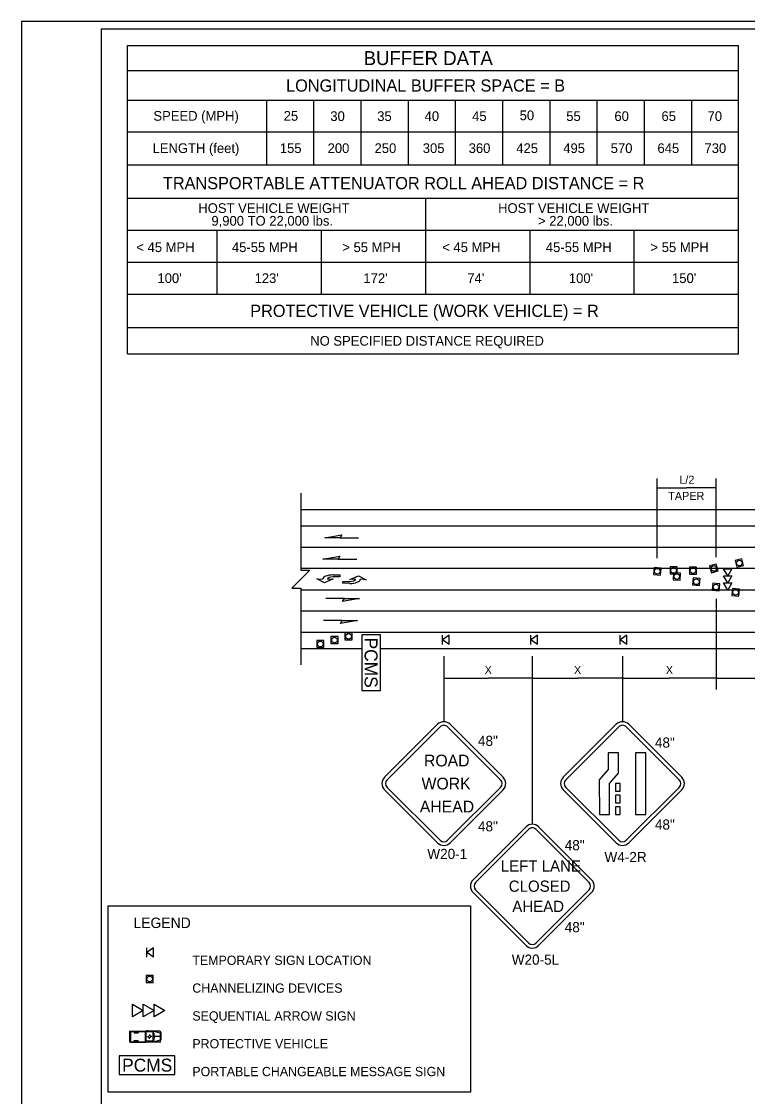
# Model space of a CAD drawing. Extents: x 99988 to 100172, y 99995 to 100047.
# Drawn here: x 99999.31 to 100005.58, y 100001.16 to 100010.44 of the extents above; entities that cross this region are included whole.
import ezdxf

# ---------------------------------------------------------------- set-up
doc = ezdxf.new("R2010")
doc.units = 0
for name, color, linetype in [('Default', 7, 'Continuous'), ('Level 15', 7, 'Continuous'), ('Level 20', 7, 'Continuous'), ('RD_MK_TrafficArrowType2LNew', 7, 'Continuous'), ('SH_DE_DetailBody1Text', 7, 'Continuous'), ('SH_DE_DetailHeading2Text', 7, 'Continuous'), ('SH_GI_PlotLimits', 7, 'Continuous'), ('SH_GI_SheetBorder', 7, 'Continuous'), ('SH_GI_TrafficMvmntArrowRt1Lane', 7, 'Continuous'), ('SH_TI_BufferDataNote', 7, 'Continuous'), ('SH_TI_SignSpacing35to70Note', 7, 'Continuous'), ('TR_SN_WarningSigns', 7, 'Continuous'), ('TR_WZ_PortableChangeMessageSign', 7, 'Continuous'), ('TR_WZ_SequentialArrowTypeC', 7, 'Continuous'), ('TR_WZ_TrafficSafetyCone', 7, 'Continuous'), ('TR_WZ_TruckBuffer', 7, 'Continuous'), ('TR_WZ_WorkZoneDetails', 7, 'Continuous')]:
    doc.layers.add(name, color=color, linetype=linetype)

msp = doc.modelspace()

# ---------------------------------------------------------------- linework, layer by layer
at = {"layer": 'Default'}
for p, q in [((100013.6062, 100005.718), (100001.7239, 100005.7184)), ((100003.0033, 100005.1415), (100002.9456, 100005.1012)), ((100002.9456, 100005.0611), (100002.9456, 100005.1415)), ((100003.0033, 100005.0611), (100003.0033, 100005.1415)), ((100003.7638, 100005.1415), (100003.706, 100005.1012)), ((100003.706, 100005.0611), (100003.706, 100005.1415)), ((100003.7638, 100005.0611), (100003.7638, 100005.1415)), ((100004.535, 100005.1415), (100004.4772, 100005.1012)), ((100004.4772, 100005.0611), (100004.4772, 100005.1415)), ((100004.535, 100005.0611), (100004.535, 100005.1415)), ((100003.0033, 100005.0611), (100002.9456, 100005.1012)), ((100003.7638, 100005.0611), (100003.706, 100005.1012)), ((100004.535, 100005.0611), (100004.4772, 100005.1012)), ((100000.4507, 100002.4443), (100000.3929, 100002.404)), ((100000.3929, 100002.3638), (100000.3929, 100002.4443)), ((100000.4507, 100002.3638), (100000.4507, 100002.4443)), ((100000.4507, 100002.3638), (100000.3929, 100002.404))]:
    msp.add_line(p, q, dxfattribs=at)
at = {"layer": 'Level 15'}
for p, q in [((100004.7981, 100006.4143), (100005.0516, 100006.4143)), ((100005.3052, 100006.4143), (100005.0516, 100006.4143)), ((100002.9568, 100004.7726), (100003.3385, 100004.7726)), ((100003.7203, 100004.7726), (100003.3385, 100004.7726)), ((100003.7203, 100004.7726), (100004.1094, 100004.7726)), ((100004.4984, 100004.7726), (100004.1094, 100004.7726)), ((100004.4984, 100004.7726), (100004.9018, 100004.7726)), ((100005.3052, 100004.7726), (100004.9018, 100004.7726)), ((100005.3052, 100004.7726), (100005.7422, 100004.7726))]:
    msp.add_line(p, q, dxfattribs=at)
at = {"layer": 'RD_MK_TrafficArrowType2LNew'}
for p, q in [((100001.91, 100005.6248), (100001.91, 100005.6248)), ((100001.9517, 100005.6248), (100001.9517, 100005.6248)), ((100002.0017, 100005.6623), (100002.0017, 100005.6623)), ((100002.0017, 100005.6623), (100002.0017, 100005.6623)), ((100002.0017, 100005.6456), (100002.0017, 100005.6456)), ((100002.1447, 100005.6061), (100002.1447, 100005.6061)), ((100002.1949, 100005.6264), (100002.1949, 100005.6264)), ((100002.2366, 100005.626), (100002.2366, 100005.626)), ((100002.1445, 100005.5895), (100002.1445, 100005.5895)), ((100002.1445, 100005.5895), (100002.1445, 100005.5895))]:
    msp.add_line(p, q, dxfattribs=at)
for points in [[(100001.9517, 100005.6248), (100002.0017, 100005.6289), (100001.9267, 100005.5956), (100001.86, 100005.6289), (100001.91, 100005.6248)], [(100002.0017, 100005.6623), (100002.06, 100005.6623), (100002.06, 100005.6456), (100002.0017, 100005.6456)], [(100002.1445, 100005.5895), (100002.0862, 100005.59), (100002.0864, 100005.6067), (100002.1447, 100005.6061)], [(100002.1949, 100005.6264), (100002.1449, 100005.6228), (100002.2202, 100005.6554), (100002.2865, 100005.6214), (100002.2366, 100005.626)]]:
    msp.add_lwpolyline(points, dxfattribs=at)
for centre, major_axis, ratio, start_param in [((100002.0017, 100005.6248), (-0.0917, 0), 0.40879, 4.712524), ((100002.0017, 100005.6248), (-0.05, 0), 0.41611, 4.712518), ((100002.1449, 100005.6269), (0.0917, -0.0009), 0.40879, 4.712524), ((100002.1449, 100005.6269), (0.05, -0.0005), 0.41611, 4.712518)]:
    msp.add_ellipse(centre, major_axis=major_axis, ratio=ratio, start_param=start_param, end_param=6.283185, dxfattribs=at)
at = {"layer": 'SH_GI_PlotLimits'}
msp.add_lwpolyline([(99999.3125, 99999.9375), (100015.8125, 99999.9375), (100015.8125, 100010.4375), (99999.3125, 100010.4375)], close=True, dxfattribs=at)
at = {"layer": 'SH_GI_SheetBorder'}
for q in [(100000, 100000), (100015.75, 100010.375)]:
    msp.add_line((100000, 100010.375), q, dxfattribs=at)
at = {"layer": 'SH_GI_TrafficMvmntArrowRt1Lane'}
for p, q in [((100002.0608, 100005.9824), (100002.2215, 100005.9824)), ((100002.044, 100005.7996), (100002.2047, 100005.7996)), ((100002.0982, 100005.4579), (100001.9375, 100005.4579)), ((100002.0803, 100005.2703), (100001.9196, 100005.2703))]:
    msp.add_line(p, q, dxfattribs=at)
for points in [[(100001.9298, 100005.9824), (100002.0757, 100006.0081), (100002.0608, 100005.9824)], [(100001.9129, 100005.7996), (100002.0588, 100005.8253), (100002.044, 100005.7996)], [(100002.2292, 100005.4579), (100002.0833, 100005.4322), (100002.0982, 100005.4579)], [(100002.2113, 100005.2703), (100002.0655, 100005.2446), (100002.0803, 100005.2703)]]:
    msp.add_lwpolyline(points, close=True, dxfattribs=at)
at = {"layer": 'SH_TI_BufferDataNote'}
for p, q in [((100000.2269, 100010.2301), (100005.5002, 100010.2301)), ((100000.2269, 100008.086), (100000.2269, 100010.2301)), ((100005.5002, 100007.57), (100005.5002, 100010.2301)), ((100000.2269, 100010.0156), (100005.5002, 100010.0156)), ((100000.2269, 100009.7584), (100005.5002, 100009.7584)), ((100001.4252, 100009.7584), (100001.4252, 100009.2011)), ((100001.8327, 100009.7584), (100001.8327, 100009.2011)), ((100002.2402, 100009.7584), (100002.2402, 100009.2011)), ((100002.6477, 100009.7584), (100002.6477, 100009.2011)), ((100003.0552, 100009.7584), (100003.0552, 100009.2011)), ((100003.4627, 100009.7584), (100003.4627, 100009.2011)), ((100003.8702, 100009.7584), (100003.8702, 100009.2011)), ((100004.2777, 100009.7584), (100004.2777, 100009.2011)), ((100004.6852, 100009.7584), (100004.6852, 100009.2011)), ((100005.0927, 100009.7584), (100005.0927, 100009.2011)), ((100000.2269, 100009.4862), (100005.5002, 100009.4862)), ((100000.2269, 100009.2011), (100005.5002, 100009.2011)), ((100000.2269, 100008.914), (100005.5002, 100008.914)), ((100002.8002, 100008.086), (100002.8002, 100008.9116)), ((100000.2269, 100008.638), (100005.5002, 100008.638)), ((100000.2269, 100007.57), (100000.2269, 100008.638)), ((100001.0004, 100008.086), (100001.0004, 100008.638)), ((100001.9004, 100008.086), (100001.9004, 100008.638)), ((100002.8004, 100008.086), (100002.8004, 100008.638)), ((100003.7004, 100008.086), (100003.7004, 100008.638)), ((100004.6004, 100008.086), (100004.6004, 100008.638)), ((100000.2269, 100008.362), (100005.5002, 100008.362)), ((100000.2269, 100008.086), (100005.5002, 100008.086)), ((100000.2269, 100007.798), (100005.5002, 100007.798)), ((100000.2269, 100007.57), (100005.5002, 100007.57))]:
    msp.add_line(p, q, dxfattribs=at)
at = {"layer": 'SH_TI_SignSpacing35to70Note'}
msp.add_lwpolyline([(100000.0599, 100002.8067), (100003.1855, 100002.8067), (100003.1855, 100001.1989), (100000.0599, 100001.1989)], close=True, dxfattribs=at)
at = {"layer": 'TR_SN_WarningSigns'}
for p, q in [((100002.4455, 100003.9167), (100002.9024, 100004.3736)), ((100002.4672, 100003.8949), (100002.9241, 100004.3518)), ((100002.9894, 100004.3518), (100003.4463, 100003.8949)), ((100003.0112, 100004.3736), (100003.4681, 100003.9167)), ((100003.9871, 100003.9167), (100004.444, 100004.3736)), ((100004.0088, 100003.8949), (100004.4657, 100004.3518)), ((100004.531, 100004.3518), (100004.9879, 100003.8949)), ((100004.5528, 100004.3736), (100005.0097, 100003.9167)), ((100002.9024, 100003.351), (100002.4455, 100003.8079)), ((100002.9241, 100003.3727), (100002.4672, 100003.8296)), ((100003.4463, 100003.8296), (100002.9894, 100003.3727)), ((100003.4681, 100003.8079), (100003.0111, 100003.351)), ((100004.444, 100003.351), (100003.9871, 100003.8079)), ((100004.4657, 100003.3728), (100004.0088, 100003.8296)), ((100004.9879, 100003.8296), (100004.531, 100003.3728)), ((100005.0097, 100003.8079), (100004.5528, 100003.351)), ((100003.209, 100003.0315), (100003.6659, 100003.4883)), ((100003.2308, 100003.0097), (100003.6877, 100003.4666)), ((100003.7529, 100003.4666), (100004.2099, 100003.0097)), ((100003.7747, 100003.4883), (100004.2316, 100003.0315)), ((100003.6659, 100002.4658), (100003.209, 100002.9227)), ((100003.6877, 100002.4875), (100003.2308, 100002.9444)), ((100004.2099, 100002.9444), (100003.7529, 100002.4875)), ((100004.2316, 100002.9227), (100003.7747, 100002.4658))]:
    msp.add_line(p, q, dxfattribs=at)
for points in [[(100004.3752, 100004.1289), (100004.3752, 100003.9851), (100004.2973, 100003.8959), (100004.3012, 100003.5956), (100004.3869, 100003.5956), (100004.3869, 100003.8623), (100004.4648, 100003.9515), (100004.4648, 100004.1289)], [(100004.6098, 100003.5956), (100004.6994, 100003.5956), (100004.6994, 100004.1289), (100004.6098, 100004.1289)], [(100004.438, 100003.7956), (100004.4776, 100003.7956), (100004.4776, 100003.8623), (100004.438, 100003.8623)], [(100004.438, 100003.6956), (100004.4776, 100003.6956), (100004.4776, 100003.7623), (100004.438, 100003.7623)], [(100004.438, 100003.5956), (100004.4776, 100003.5956), (100004.4776, 100003.6623), (100004.438, 100003.6623)]]:
    msp.add_lwpolyline(points, close=True, dxfattribs=at)
for centre, radius, start, end in [((100002.9568, 100004.3192), 0.0769, 44.99628, 134.99965), ((100004.4984, 100004.3192), 0.0769, 44.99628, 134.99965), ((100002.9568, 100004.3192), 0.0462, 44.99628, 134.99965), ((100004.4984, 100004.3192), 0.0462, 44.99628, 134.99965), ((100002.4999, 100003.8623), 0.0769, 134.99658, 224.99358), ((100002.4999, 100003.8623), 0.0462, 134.99658, 224.99358), ((100003.4137, 100003.8623), 0.0462, 314.99936, 44.99485), ((100003.4137, 100003.8623), 0.0769, 314.99936, 44.99485), ((100004.0415, 100003.8623), 0.0769, 134.99658, 224.99358), ((100004.0415, 100003.8623), 0.0462, 134.99658, 224.99358), ((100004.9553, 100003.8623), 0.0462, 314.99936, 44.99485), ((100004.9553, 100003.8623), 0.0769, 314.99936, 44.99485), ((100003.7203, 100003.434), 0.0769, 44.99628, 134.99965), ((100003.7203, 100003.434), 0.0462, 44.99628, 134.99965), ((100002.9568, 100003.4054), 0.0462, 225, 314.99958), ((100004.4984, 100003.4054), 0.0462, 225, 314.99958), ((100002.9568, 100003.4054), 0.0769, 225, 314.99958), ((100004.4984, 100003.4054), 0.0769, 225, 314.99958), ((100003.2634, 100002.9771), 0.0769, 134.99658, 224.99358), ((100003.2634, 100002.9771), 0.0462, 134.99658, 224.99358), ((100004.1772, 100002.9771), 0.0462, 314.99936, 44.99485), ((100004.1772, 100002.9771), 0.0769, 314.99936, 44.99485), ((100003.7203, 100002.5202), 0.0769, 225, 314.99958), ((100003.7203, 100002.5202), 0.0462, 225, 314.99958)]:
    msp.add_arc(centre, radius, start, end, dxfattribs=at)
at = {"layer": 'TR_WZ_PortableChangeMessageSign'}
for points in [[(100002.2488, 100005.1464), (100002.2488, 100004.6664), (100002.4088, 100004.6664), (100002.4088, 100005.1464)], [(100000.1561, 100001.3529), (100000.6361, 100001.3529), (100000.6361, 100001.5129), (100000.1561, 100001.5129)]]:
    msp.add_lwpolyline(points, close=True, dxfattribs=at)
at = {"layer": 'TR_WZ_SequentialArrowTypeC'}
for points in [[(100005.3706, 100005.7154), (100005.4415, 100005.7154), (100005.4061, 100005.6542), (100005.4415, 100005.6542), (100005.4061, 100005.593), (100005.4415, 100005.593), (100005.4061, 100005.5318), (100005.3706, 100005.593), (100005.4061, 100005.593), (100005.3706, 100005.6542), (100005.4061, 100005.6542)], [(100000.27, 100001.8501), (100000.27, 100001.9582), (100000.3632, 100001.9042), (100000.3632, 100001.9582), (100000.4566, 100001.9042), (100000.4566, 100001.9582), (100000.5498, 100001.9042), (100000.4566, 100001.8501), (100000.4566, 100001.9042), (100000.3632, 100001.8501), (100000.3632, 100001.9042)]]:
    msp.add_lwpolyline(points, close=True, dxfattribs=at)
at = {"layer": 'TR_WZ_TrafficSafetyCone'}
for points in [[(100005.4692, 100005.7868), (100005.4849, 100005.7281), (100005.5436, 100005.7438), (100005.5279, 100005.8025)], [(100004.8257, 100005.6613), (100004.831, 100005.7218), (100004.7705, 100005.7271), (100004.7652, 100005.6666)], [(100004.9087, 100005.6711), (100004.9694, 100005.6711), (100004.9694, 100005.7318), (100004.9087, 100005.7318)], [(100005.0762, 100005.6696), (100005.1369, 100005.6696), (100005.1369, 100005.7303), (100005.0762, 100005.7303)], [(100005.2491, 100005.74), (100005.2649, 100005.6813), (100005.3235, 100005.697), (100005.3078, 100005.7557)], [(100004.9947, 100005.616), (100005, 100005.6765), (100004.9395, 100005.6818), (100004.9342, 100005.6213)], [(100005.1637, 100005.5707), (100005.169, 100005.6312), (100005.1085, 100005.6365), (100005.1032, 100005.576)], [(100005.3328, 100005.5254), (100005.3381, 100005.5859), (100005.2776, 100005.5912), (100005.2723, 100005.5307)], [(100005.5018, 100005.4801), (100005.5071, 100005.5406), (100005.4466, 100005.5459), (100005.4413, 100005.4854)], [(100002.1039, 100005.102), (100002.1646, 100005.102), (100002.1646, 100005.1628), (100002.1039, 100005.1628)], [(100001.8605, 100005.0356), (100001.9212, 100005.0356), (100001.9212, 100005.0964), (100001.8605, 100005.0964)], [(100001.9829, 100005.0702), (100002.0436, 100005.0702), (100002.0436, 100005.131), (100001.9829, 100005.131)], [(100000.4485, 100002.2073), (100000.3878, 100002.2062), (100000.3888, 100002.1455), (100000.4496, 100002.1465)]]:
    msp.add_lwpolyline(points, close=True, dxfattribs=at)
for centre in [(100005.5064, 100005.7653), (100004.7981, 100005.6942), (100004.9391, 100005.7014), (100005.1066, 100005.7), (100005.2863, 100005.7185), (100004.9671, 100005.6489), (100005.1361, 100005.6036), (100005.3052, 100005.5583), (100005.4742, 100005.513), (100002.1342, 100005.1324), (100001.8909, 100005.066), (100002.0133, 100005.1006), (100000.4187, 100002.1764)]:
    msp.add_circle(centre, 0.0244, dxfattribs=at)
at = {"layer": 'TR_WZ_TruckBuffer'}
for p, q in [((100000.2439, 100001.7222), (100000.2439, 100001.6358)), ((100000.2469, 100001.7251), (100000.2498, 100001.7251)), ((100000.2498, 100001.7251), (100000.2498, 100001.6329)), ((100000.2502, 100001.7266), (100000.3842, 100001.7266)), ((100000.2502, 100001.7266), (100000.2502, 100001.6313)), ((100000.254, 100001.7228), (100000.254, 100001.6351)), ((100000.254, 100001.7228), (100000.3804, 100001.7228)), ((100000.2842, 100001.7228), (100000.2842, 100001.7119)), ((100000.2842, 100001.7119), (100000.32, 100001.7119)), ((100000.2914, 100001.7228), (100000.2914, 100001.7119)), ((100000.3135, 100001.7228), (100000.3135, 100001.7119)), ((100000.32, 100001.7228), (100000.32, 100001.7119)), ((100000.3804, 100001.7228), (100000.3804, 100001.6351)), ((100000.3842, 100001.7266), (100000.3842, 100001.6313)), ((100000.386, 100001.7266), (100000.386, 100001.6313)), ((100000.5091, 100001.7266), (100000.386, 100001.7266)), ((100000.4464, 100001.7193), (100000.386, 100001.7193)), ((100000.4028, 100001.728), (100000.3954, 100001.728)), ((100000.4464, 100001.7266), (100000.4386, 100001.7193)), ((100000.4464, 100001.7266), (100000.4464, 100001.6313)), ((100000.4475, 100001.7266), (100000.4475, 100001.6313)), ((100000.5091, 100001.7092), (100000.4475, 100001.7266)), ((100000.5091, 100001.7266), (100000.5091, 100001.6313)), ((100000.5091, 100001.7266), (100000.5151, 100001.7074)), ((100000.5151, 100001.7074), (100000.5151, 100001.6506)), ((100000.2439, 100001.6857), (100000.2498, 100001.6839)), ((100000.2439, 100001.6723), (100000.2498, 100001.6741)), ((100000.2455, 100001.679), (100000.2482, 100001.679)), ((100000.2469, 100001.6803), (100000.2469, 100001.6776)), ((100000.2469, 100001.6329), (100000.2498, 100001.6329)), ((100000.2502, 100001.6313), (100000.3842, 100001.6313)), ((100000.254, 100001.6351), (100000.3804, 100001.6351)), ((100000.2842, 100001.6351), (100000.2842, 100001.6461)), ((100000.2842, 100001.6461), (100000.32, 100001.6461)), ((100000.2914, 100001.6351), (100000.2914, 100001.6461)), ((100000.3135, 100001.6351), (100000.3135, 100001.6461)), ((100000.32, 100001.6351), (100000.32, 100001.6461)), ((100000.4464, 100001.6387), (100000.386, 100001.6387)), ((100000.5091, 100001.6313), (100000.386, 100001.6313)), ((100000.4028, 100001.63), (100000.3954, 100001.63)), ((100000.3968, 100001.6786), (100000.4065, 100001.6788)), ((100000.4077, 100001.6788), (100000.4077, 100001.6788)), ((100000.4164, 100001.6607), (100000.4166, 100001.6678)), ((100000.4169, 100001.6979), (100000.4169, 100001.6902)), ((100000.4365, 100001.679), (100000.4283, 100001.679)), ((100000.4399, 100001.6387), (100000.4464, 100001.6313)), ((100000.5091, 100001.6488), (100000.4475, 100001.6313)), ((100000.5091, 100001.679), (100000.4596, 100001.679)), ((100000.5091, 100001.6313), (100000.5151, 100001.6506))]:
    msp.add_line(p, q, dxfattribs=at)
for centre, radius in [((100000.2469, 100001.679), 0.00134), ((100000.4169, 100001.679), 0.00918)]:
    msp.add_circle(centre, radius, dxfattribs=at)
for centre, radius, start, end in [((100000.2469, 100001.7222), 0.00291, 90, 179.99999), ((100000.3596, 100001.679), 0.1, 331.55054, 28.46005), ((100000.2469, 100001.6358), 0.00291, 180, 270)]:
    msp.add_arc(centre, radius, start, end, dxfattribs=at)
at = {"layer": 'TR_WZ_WorkZoneDetails'}
for p, q in [((100004.7981, 100005.8072), (100004.7981, 100006.4943)), ((100005.3052, 100005.8168), (100005.3052, 100006.4943)), ((100001.7239, 100006.2268), (100012.9775, 100006.2268)), ((100001.7239, 100006.0851), (100013.6062, 100006.0851)), ((100001.7239, 100005.9017), (100013.6059, 100005.9017)), ((100001.7239, 100005.535), (100013.6062, 100005.535)), ((100005.3052, 100005.4571), (100005.3052, 100004.6726)), ((100001.7239, 100005.3517), (100013.6062, 100005.3517)), ((100001.7276, 100005.1683), (100013.5994, 100005.1683)), ((100001.7239, 100005.0266), (100002.2436, 100005.0266)), ((100002.4167, 100005.0266), (100013.6016, 100005.0266)), ((100002.9568, 100004.9611), (100002.9568, 100004.3961)), ((100003.7203, 100004.9611), (100003.7203, 100003.5109)), ((100004.4984, 100004.9611), (100004.4984, 100004.3961))]:
    msp.add_line(p, q, dxfattribs=at)
msp.add_lwpolyline([(100001.7239, 100006.3668), (100001.7239, 100005.7041), (100001.8013, 100005.7041), (100001.6465, 100005.5493), (100001.7239, 100005.5493), (100001.7239, 100004.8866)], dxfattribs=at)

# ---------------------------------------------------------------- texts
at = {"layer": 'Level 20'}
for s, p in [('L/2', (100004.9889, 100006.4493)), ('TAPER', (100004.8926, 100006.3093)), ('X', (100004.8721, 100004.8076))]:
    msp.add_text(s, height=0.07, dxfattribs=at).set_placement(p)
for p in [(100003.3088, 100004.8076), (100004.0796, 100004.8076)]:
    msp.add_text('X', height=0.07, rotation=360, dxfattribs=at).set_placement(p)
at = {"layer": 'SH_DE_DetailBody1Text'}
for s, p in [('TEMPORARY SIGN LOCATION', (100000.7867, 100002.2977)), ('CHANNELIZING DEVICES', (100000.7867, 100002.0577)), ('SEQUENTIAL ARROW SIGN', (100000.7867, 100001.8177)), ('PROTECTIVE VEHICLE', (100000.7867, 100001.5777)), ('PORTABLE CHANGEABLE MESSAGE SIGN', (100000.7867, 100001.3377))]:
    msp.add_text(s, height=0.08, dxfattribs=at).set_placement(p)
at = {"layer": 'SH_DE_DetailHeading2Text'}
msp.add_text('LEGEND', height=0.09, dxfattribs=at).set_placement((100000.2783, 100002.6159))
at = {"layer": 'SH_TI_BufferDataNote'}
for s, height, p in [('BUFFER DATA', 0.12, (100002.2648, 100010.0616)), ('LONGITUDINAL BUFFER SPACE = B', 0.105, (100001.5957, 100009.8328)), ('SPEED (MPH)', 0.084, (100000.451, 100009.5812)), ('25', 0.084, (100001.5747, 100009.5812)), ('30', 0.084, (100001.9773, 100009.5788)), ('35', 0.084, (100002.382, 100009.5788)), ('40', 0.084, (100002.7908, 100009.5788)), ('45', 0.084, (100003.201, 100009.5788)), ('50', 0.084, (100003.6112, 100009.586)), ('55', 0.084, (100004.013, 100009.5788)), ('60', 0.084, (100004.4285, 100009.5788)), ('65', 0.084, (100004.8349, 100009.5788)), ('70', 0.084, (100005.2324, 100009.5788)), ('LENGTH (feet)', 0.084, (100000.4434, 100009.3026)), ('155', 0.084, (100001.5417, 100009.3026)), ('200', 0.084, (100001.9539, 100009.3026)), ('250', 0.084, (100002.3589, 100009.3026)), ('305', 0.084, (100002.7749, 100009.3026)), ('360', 0.084, (100003.1709, 100009.3026)), ('425', 0.084, (100003.5821, 100009.3026)), ('495', 0.084, (100003.9873, 100009.3026)), ('570', 0.084, (100004.3967, 100009.3026)), ('645', 0.084, (100004.8, 100009.3026)), ('730', 0.084, (100005.2057, 100009.3026)), ('TRANSPORTABLE ATTENUATOR ROLL AHEAD DISTANCE = R', 0.105, (100000.5327, 100008.9907)), ('HOST VEHICLE WEIGHT', 0.084, (100000.8383, 100008.7854)), ('HOST VEHICLE WEIGHT', 0.084, (100003.425, 100008.7854)), ('9,900 TO 22,000 lbs.', 0.084, (100000.9512, 100008.676)), ('> 22,000 lbs.', 0.084, (100003.7694, 100008.676)), ('< 45 MPH', 0.084, (100000.3036, 100008.4482)), ('45-55 MPH', 0.084, (100001.1282, 100008.4482)), ('> 55 MPH', 0.084, (100002.0808, 100008.4482)), ('< 45 MPH', 0.084, (100002.9429, 100008.4482)), ('45-55 MPH', 0.084, (100003.8371, 100008.4482)), ('> 55 MPH', 0.084, (100004.7401, 100008.4482)), ("100'", 0.084, (100000.4854, 100008.1809)), ("123'", 0.084, (100001.3238, 100008.1809)), ("172'", 0.084, (100002.2627, 100008.1809)), ("74'", 0.084, (100003.1593, 100008.1809)), ("100'", 0.084, (100004.0355, 100008.1809)), ("150'", 0.084, (100004.9259, 100008.1809)), ('PROTECTIVE VEHICLE (WORK VEHICLE) = R', 0.105, (100001.2861, 100007.8889)), ('NO SPECIFIED DISTANCE REQUIRED', 0.084, (100001.804, 100007.6401))]:
    msp.add_text(s, height=height, dxfattribs=at).set_placement(p)
at = {"layer": 'TR_SN_WarningSigns'}
for s, height, p in [('48"', 0.0875, (100003.2513, 100004.187)), ('48"', 0.0875, (100004.7779, 100004.1721)), ('ROAD', 0.10176, (100002.7855, 100004.0101)), ('WORK', 0.10176, (100002.7646, 100003.8114)), ('AHEAD', 0.10176, (100002.7493, 100003.6128)), ('48"', 0.0875, (100003.2513, 100003.45)), ('48"', 0.0875, (100004.7779, 100003.465)), ('48"', 0.0875, (100003.9999, 100003.2869)), ('W20-1', 0.0875, (100002.8143, 100003.2116)), ('LEFT LANE', 0.09691, (100003.4481, 100003.103)), ('W4-2R', 0.0875, (100004.3428, 100003.1847)), ('CLOSED', 0.09691, (100003.517, 100002.9286)), ('AHEAD', 0.09691, (100003.5474, 100002.7542)), ('48"', 0.0875, (100003.9999, 100002.5798)), ('W20-5L', 0.0875, (100003.5425, 100002.2995))]:
    msp.add_text(s, height=height, dxfattribs=at).set_placement(p)
at = {"layer": 'TR_WZ_PortableChangeMessageSign'}
for rotation, p in [(270, (100002.2728, 100005.1219)), (360, (100000.1806, 100001.3769))]:
    msp.add_text('PCMS', height=0.112, rotation=rotation, dxfattribs=at).set_placement(p)

doc.saveas('drawing.dxf')
